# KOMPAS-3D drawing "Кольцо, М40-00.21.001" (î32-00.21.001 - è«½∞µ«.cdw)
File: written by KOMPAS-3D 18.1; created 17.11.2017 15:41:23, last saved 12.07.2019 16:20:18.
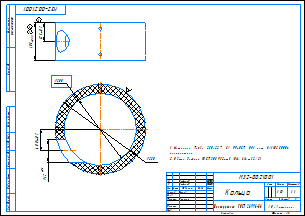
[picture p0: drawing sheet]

Sheet 1: A3, landscape

Document properties: Масса: 1.57813; Полное имя файла: М32-00.21.001 - Кольцо.m3d

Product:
- Part/product: (unnamed)  | designation М32-00.21.001-01
- Part/product: Кольцо  | designation М40-00.21.001
    Материал: Полипропилен  ГОСТ 26996-86 (density 900 kg/m3)
    Масса: 1.59002
    Раздел спецификации: Детали
    Форматы листов документа: A3
    source file: ..\Магна ins 40\3Д\М40-00.21.001 - Кольцо.cdw
- Part/product: Кольцо  | designation М32-00.21.001
    Материал: Полипропилен  ГОСТ 26996-86 (density 900 kg/m3)
    Масса: 1.66598
    source file: М32-00.21.001 - Кольцо.cdw
- Part/product: Кольцо  | designation М32-00.21.001
    Материал: Полипропилен  ГОСТ 26996-86 (density 900 kg/m3)
    Масса: 1.57813
  - Body: Тело 1
      Материал: Полипропилен  ГОСТ 26996-86 (density 0.9 kg/m3)
  - Body: Тело 6
      Материал: Полипропилен  ГОСТ 26996-86 (density 0.9 kg/m3)

Title block, sheet 1: Наименование: Кольцо; designation: М32-00.21.001; Материал: Полипропилен  ГОСТ 26996-86; Масса: 1,58; scale: 1:1; Количество листов документа: 1; organisation: АО «Астерион»; Форматы листов документа: A3; stored path: D:\Отработать\Магна 40\Чертежи\М40-00.20.001 - Кольцо.cdw; Разработал: Милов; Т. контр.: Лучихин

Views: Проекционный вид 3, Местный разрез 1, Вид:1, Проекционный вид 4, Вид:2
Referenced files in D:\Magna\Магна Ins\Магна ins 32\: М32-00.21.001 - Кольцо.m3d
Referenced files in D:\Отработать\Магна 40\3Д\: Кольцо-7.m3d
Referenced files in \\192.168.87.28\Konstructor_doc\Магна\Магна Ins\Магна ins 32\: М32-00.21.001 - Кольцо.m3d, М32-00.20.001 - Кольцо.m3d
Referenced files in D:\Magna\Магна Ins\Магна ins 32\Для Караби\: М32-00.21.001 - Кольцо.m3d
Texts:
  Лифлянд
Dimensions and other numbers on the sheet: 60,01±0,2; 62; 250; 200; 1; 2; 52,5±0,2; 105; 1:1; 1,58; 19.04.2019; 12.07.2019

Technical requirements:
  Материал: Труба 250х22,7 FV PP-RCT UNI арт. ВА110250004
  полипропилен.
  Общие допуски ГОСТ 30893.2-mK (H14, h14,  t2/2).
